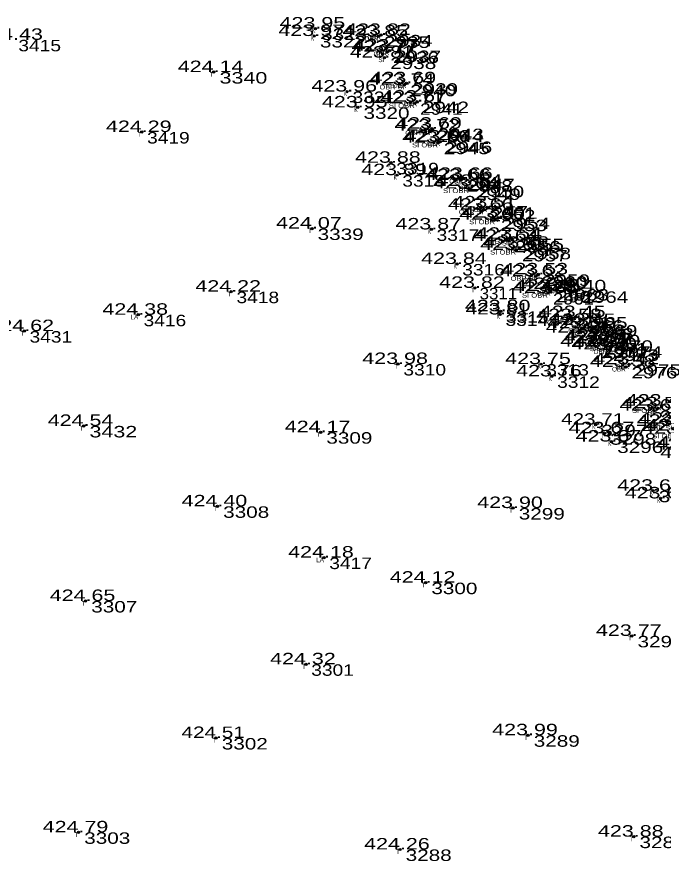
# Model space of a CAD drawing. Extents: x -639390 to -639074, y -1138747 to -1138358.
# Drawn here: x -639264.4 to -639222.1, y -1138514.5 to -1138459.3 of the extents above; entities that cross this region are included whole.
import ezdxf
from ezdxf.enums import TextEntityAlignment as Align

# ---------------------------------------------------------------- set-up
doc = ezdxf.new("R2010")
doc.units = 0
doc.header["$LTSCALE"] = 0.3
doc.header["$PDMODE"] = 32
doc.header["$PDSIZE"] = 0.15
for name, color, linetype in [('11', 7, 'Continuous'), ('12', 7, 'Continuous'), ('13', 7, 'Continuous'), ('57', 7, 'Continuous')]:
    doc.layers.add(name, color=color, linetype=linetype)

msp = doc.modelspace()

# ---------------------------------------------------------------- linework, layer by layer
at = {"layer": '11'}
for p in [(-639244.84, -1138460.09), (-639244.92, -1138460.58), (-639240.73, -1138460.61), (-639240.55, -1138460.51), (-639240.14, -1138461.6), (-639240, -1138461.53), (-639240.32, -1138461.99), (-639251.5, -1138462.94), (-639239.01, -1138463.77), (-639238.89, -1138463.67), (-639242.76, -1138464.21), (-639238.34, -1138464.98), (-639238.18, -1138464.87), (-639242.07, -1138465.25), (-639237.33, -1138466.76), (-639237.21, -1138466.64), (-639256.2, -1138466.86), (-639236.82, -1138467.56), (-639236.66, -1138467.48), (-639239.9, -1138468.87), (-639239.5, -1138469.68), (-639235.32, -1138470), (-639235.19, -1138469.92), (-639234.79, -1138470.55), (-639234.57, -1138470.38), (-639233.83, -1138471.94), (-639233.6, -1138471.79), (-639233.08, -1138472.59), (-639232.88, -1138472.45), (-639245.07, -1138473.17), (-639237.26, -1138473.23), (-639231.97, -1138473.84), (-639232.18, -1138473.98), (-639231.5, -1138474.43), (-639231.71, -1138474.57), (-639235.58, -1138475.49), (-639230.43, -1138476.29), (-639230.26, -1138476.17), (-639234.4, -1138477.05), (-639229.46, -1138477.25), (-639229.02, -1138477.13), (-639250.35, -1138477.3), (-639229.63, -1138477.39), (-639227.76, -1138477.28), (-639256.43, -1138478.81), (-639232.75, -1138478.79), (-639232.72, -1138478.58), (-639228.05, -1138479.16), (-639227.81, -1138478.96), (-639227.16, -1138479.48), (-639263.89, -1138479.88), (-639227.5, -1138479.98), (-639227.4, -1138479.69), (-639226.15, -1138480.48), (-639226.48, -1138480.89), (-639226.3, -1138480.66), (-639225.75, -1138481.08), (-639225.54, -1138480.87), (-639239.43, -1138482.03), (-639230.08, -1138482.04), (-639224.54, -1138482.22), (-639224.31, -1138482.05), (-639229.37, -1138482.84), (-639222.43, -1138484.93), (-639222.19, -1138484.75), (-639222.69, -1138485.08), (-639260.01, -1138486.08), (-639226.51, -1138486), (-639244.5, -1138486.49), (-639225.93, -1138486.56), (-639225.47, -1138487.1), (-639222.75, -1138490.32), (-639222.26, -1138490.82), (-639251.25, -1138491.34), (-639231.91, -1138491.45), (-639244.28, -1138494.69), (-639237.63, -1138496.33), (-639259.88, -1138497.53), (-639224.14, -1138499.81), (-639245.46, -1138501.67), (-639251.34, -1138506.49), (-639230.93, -1138506.31), (-639260.34, -1138512.66), (-639224.01, -1138512.94), (-639239.31, -1138513.78)]:
    msp.add_point(p, dxfattribs=at)

# ---------------------------------------------------------------- texts
at = {"layer": '12'}
for s, width, p in [('423.95 ', 1.4, (-639244.84, -1138460.09)), ('424.43 ', 1.4, (-639264.62, -1138460.83)), ('423.97 ', 1.4, (-639244.92, -1138460.58)), ('423.85 ', 1.4, (-639240.73, -1138460.61)), ('423.82 ', 1.4, (-639240.55, -1138460.51)), ('423.77 ', 1.4, (-639240.14, -1138461.6)), ('423.77 ', 1.4, (-639240, -1138461.53)), ('423.81 ', 1.35, (-639240.319, -1138461.99)), ('424.14 ', 1.4, (-639251.5, -1138462.94)), ('423.74 ', 1.4, (-639239.01, -1138463.77)), ('423.69 ', 1.4, (-639238.89, -1138463.67)), ('423.96 ', 1.4, (-639242.759, -1138464.21)), ('423.95 ', 1.4, (-639242.07, -1138465.25)), ('423.71 ', 1.35, (-639238.339, -1138464.98)), ('423.67 ', 1.4, (-639238.18, -1138464.87)), ('424.29 ', 1.4, (-639256.2, -1138466.86)), ('423.72 ', 1.4, (-639237.33, -1138466.76)), ('423.69 ', 1.4, (-639237.21, -1138466.64)), ('423.70 ', 1.4, (-639236.82, -1138467.56)), ('423.66 ', 1.4, (-639236.659, -1138467.48)), ('423.88 ', 1.4, (-639239.9, -1138468.87)), ('423.89 ', 1.4, (-639239.5, -1138469.68)), ('423.66 ', 1.4, (-639235.319, -1138470)), ('423.66 ', 1.4, (-639235.189, -1138469.92)), ('423.64 ', 1.4, (-639234.79, -1138470.55)), ('423.54 ', 1.4, (-639234.57, -1138470.38)), ('423.51 ', 1.35, (-639233.599, -1138471.79)), ('423.66 ', 1.4, (-639233.829, -1138471.94)), ('423.60 ', 1.4, (-639233.08, -1138472.59)), ('423.47 ', 1.4, (-639232.88, -1138472.45)), ('424.07 ', 1.4, (-639245.07, -1138473.17)), ('423.87 ', 1.4, (-639237.26, -1138473.23)), ('423.64 ', 1.4, (-639232.18, -1138473.98)), ('423.54 ', 1.4, (-639231.97, -1138473.84)), ('423.63 ', 1.4, (-639231.71, -1138474.57)), ('423.48 ', 1.4, (-639231.5, -1138474.43)), ('423.84 ', 1.4, (-639235.58, -1138475.49)), ('423.62 ', 1.4, (-639230.43, -1138476.29)), ('423.53 ', 1.4, (-639230.26, -1138476.17)), ('424.22 ', 1.4, (-639250.35, -1138477.3)), ('423.82 ', 1.4, (-639234.4, -1138477.05)), ('423.58 ', 1.4, (-639229.63, -1138477.39)), ('423.45 ', 1.4, (-639229.46, -1138477.25)), ('423.40 ', 1.4, (-639229.02, -1138477.13)), ('423.40 ', 1.4, (-639227.76, -1138477.28)), ('424.38 ', 1.4, (-639256.43, -1138478.81)), ('423.80 ', 1.4, (-639232.72, -1138478.58)), ('423.81 ', 1.35, (-639232.749, -1138478.79)), ('423.45 ', 1.4, (-639227.81, -1138478.96)), ('423.58 ', 1.4, (-639228.05, -1138479.16)), ('423.45 ', 1.4, (-639227.16, -1138479.48)), ('424.62 ', 1.4, (-639263.89, -1138479.88)), ('423.61 ', 1.35, (-639227.499, -1138479.98)), ('423.51 ', 1.35, (-639227.399, -1138479.69)), ('423.51 ', 1.35, (-639226.299, -1138480.66)), ('423.45 ', 1.4, (-639226.15, -1138480.48)), ('423.60 ', 1.4, (-639226.48, -1138480.89)), ('423.50 ', 1.4, (-639225.75, -1138481.08)), ('423.40 ', 1.4, (-639225.54, -1138480.87)), ('423.98 ', 1.4, (-639239.43, -1138482.03)), ('423.75 ', 1.4, (-639230.08, -1138482.04)), ('423.58 ', 1.4, (-639224.54, -1138482.22)), ('423.42 ', 1.4, (-639224.31, -1138482.05)), ('423.76 ', 1.4, (-639229.369, -1138482.84)), ('423.61 ', 1.35, (-639222.689, -1138485.08)), ('423.58 ', 1.4, (-639222.43, -1138484.93)), ('423.48 ', 1.4, (-639222.19, -1138484.75)), ('424.54 ', 1.4, (-639260.01, -1138486.08)), ('423.71 ', 1.35, (-639226.509, -1138486)), ('423.57 ', 1.4, (-639221.47, -1138486.07)), ('423.50 ', 1.4, (-639221.3, -1138485.93)), ('424.17 ', 1.4, (-639244.5, -1138486.49)), ('423.67 ', 1.4, (-639225.93, -1138486.56)), ('423.56 ', 1.4, (-639221.109, -1138486.59)), ('423.45 ', 1.4, (-639220.87, -1138486.38)), ('423.67 ', 1.4, (-639225.47, -1138487.1)), ('423.50 ', 1.4, (-639220.25, -1138487.64)), ('423.42 ', 1.4, (-639220.07, -1138487.49)), ('423.50 ', 1.4, (-639219.93, -1138488.18)), ('423.65 ', 1.4, (-639222.75, -1138490.32)), ('423.65 ', 1.4, (-639222.26, -1138490.82)), ('424.40 ', 1.4, (-639251.25, -1138491.34)), ('423.90 ', 1.4, (-639231.91, -1138491.45)), ('424.18 ', 1.4, (-639244.28, -1138494.69)), ('424.12 ', 1.4, (-639237.63, -1138496.33)), ('424.65 ', 1.4, (-639259.88, -1138497.53)), ('423.77 ', 1.4, (-639224.14, -1138499.81)), ('424.32 ', 1.4, (-639245.46, -1138501.67)), ('424.51 ', 1.35, (-639251.339, -1138506.49)), ('423.99 ', 1.4, (-639230.93, -1138506.31)), ('424.79 ', 1.4, (-639260.34, -1138512.66)), ('423.88 ', 1.4, (-639224.01, -1138512.94)), ('424.26 ', 1.4, (-639239.309, -1138513.78))]:
    msp.add_text(s, height=0.75, dxfattribs=dict(at, width=width)).set_placement(p, align=Align.CENTER)
at = {"layer": '13'}
for s, width, p in [(' 3323', 1.35, (-639244.84, -1138460.84)), (' 3322', 1.35, (-639244.92, -1138461.33)), (' 2935', 1.35, (-639240.73, -1138461.36)), (' 2934', 1.35, (-639240.55, -1138461.26)), (' 3415', 1.25, (-639264.62, -1138461.58)), (' 2936', 1.35, (-639240.14, -1138462.35)), (' 2937', 1.35, (-639240, -1138462.28)), (' 2938', 1.35, (-639240.32, -1138462.74)), (' 3340', 1.4, (-639251.5, -1138463.69)), (' 2940', 1.35, (-639239.01, -1138464.52)), (' 2939', 1.35, (-639238.89, -1138464.42)), (' 3321', 1.25, (-639242.76, -1138464.96)), (' 2941', 1.25, (-639238.34, -1138465.73)), (' 2942', 1.35, (-639238.18, -1138465.62)), (' 3320', 1.35, (-639242.07, -1138466)), (' 2943', 1.35, (-639237.21, -1138467.39)), (' 3419', 1.25, (-639256.2, -1138467.61)), (' 2944', 1.4, (-639237.33, -1138467.51)), (' 2945', 1.35, (-639236.82, -1138468.31)), (' 2946', 1.35, (-639236.66, -1138468.23)), (' 3319', 1.25, (-639239.9, -1138469.62)), (' 3318', 1.25, (-639239.5, -1138470.43)), (' 2948', 1.35, (-639235.32, -1138470.75)), (' 2947', 1.35, (-639235.19, -1138470.67)), (' 2949', 1.35, (-639234.79, -1138471.3)), (' 2950', 1.35, (-639234.57, -1138471.13)), (' 2952', 1.35, (-639233.83, -1138472.69)), (' 2951', 1.25, (-639233.6, -1138472.54)), (' 2953', 1.35, (-639233.08, -1138473.34)), (' 2954', 1.35, (-639232.88, -1138473.2)), (' 3339', 1.35, (-639245.07, -1138473.92)), (' 3317', 1.25, (-639237.26, -1138473.98)), (' 2955', 1.35, (-639231.97, -1138474.59)), (' 2956', 1.35, (-639232.18, -1138474.73)), (' 2958', 1.35, (-639231.5, -1138475.18)), (' 2957', 1.35, (-639231.71, -1138475.32)), (' 3316', 1.25, (-639235.58, -1138476.24)), (' 2960', 1.35, (-639230.43, -1138477.04)), (' 2959', 1.35, (-639230.26, -1138476.92)), (' 3311', 1.1, (-639234.4, -1138477.8)), (' 2963', 1.35, (-639229.02, -1138477.88)), (' 3418', 1.25, (-639250.35, -1138478.05)), (' 2961', 1.2, (-639229.63, -1138478.14)), (' 2962', 1.35, (-639229.46, -1138478)), (' 2964', 1.35, (-639227.76, -1138478.03)), (' 3416', 1.25, (-639256.43, -1138479.56)), (' 3314', 1.25, (-639232.75, -1138479.54)), (' 3315', 1.25, (-639232.72, -1138479.33)), (' 2966', 1.35, (-639228.05, -1138479.91)), (' 2965', 1.35, (-639227.81, -1138479.71)), (' 3431', 1.25, (-639263.89, -1138480.63)), (' 2968', 1.35, (-639227.4, -1138480.44)), (' 2969', 1.35, (-639227.16, -1138480.23)), (' 2967', 1.35, (-639227.5, -1138480.73)), (' 2970', 1.35, (-639226.15, -1138481.23)), (' 2972', 1.35, (-639226.48, -1138481.64)), (' 2971', 1.25, (-639226.3, -1138481.41)), (' 2974', 1.35, (-639225.54, -1138481.62)), (' 2973', 1.35, (-639225.75, -1138481.83)), (' 3310', 1.25, (-639239.43, -1138482.78)), (' 3313', 1.25, (-639230.08, -1138482.79)), (' 2975', 1.35, (-639224.31, -1138482.8)), (' 2976', 1.35, (-639224.54, -1138482.97)), (' 3312', 1.25, (-639229.37, -1138483.59)), (' 2977', 1.35, (-639222.69, -1138485.83)), (' 3297', 1.35, (-639226.51, -1138486.75)), (' 3432', 1.4, (-639260.01, -1138486.83)), (' 3309', 1.35, (-639244.5, -1138487.24)), (' 3298', 1.35, (-639225.93, -1138487.31)), (' 3296', 1.35, (-639225.47, -1138487.85)), (' 3295', 1.35, (-639222.75, -1138491.07)), (' 3308', 1.35, (-639251.25, -1138492.09)), (' 3299', 1.35, (-639231.91, -1138492.2)), (' 3417', 1.25, (-639244.28, -1138495.44)), (' 3300', 1.35, (-639237.63, -1138497.08)), (' 3307', 1.35, (-639259.88, -1138498.28)), (' 3290', 1.35, (-639224.14, -1138500.56)), (' 3301', 1.25, (-639245.46, -1138502.42)), (' 3289', 1.35, (-639230.93, -1138507.06)), (' 3302', 1.35, (-639251.34, -1138507.24)), (' 3303', 1.35, (-639260.34, -1138513.41)), (' 3282', 1.35, (-639224.01, -1138513.69)), (' 3288', 1.35, (-639239.31, -1138514.53))]:
    msp.add_text(s, height=0.75, dxfattribs=dict(at, width=width)).set_placement(p)
at = {"layer": '57'}
for s, width, p in [('K', 0.65, (-639244.919, -1138460.88)), ('K', 0.65, (-639244.839, -1138460.39)), ('OBR', 0.9, (-639240.729, -1138460.91)), ('OBR', 0.9, (-639240.549, -1138460.81)), ('OBR', 0.9, (-639240.139, -1138461.9)), ('OBR', 0.9, (-639239.999, -1138461.83)), ('SI', 1.05, (-639240.32, -1138462.29)), ('T', 0.85, (-639251.5, -1138463.24)), ('OBR SI', 1.2, (-639239.01, -1138464.07)), ('OBR', 0.9, (-639238.889, -1138463.97)), ('K', 0.65, (-639242.759, -1138464.51)), ('SI OBR', 1.25, (-639238.339, -1138465.28)), ('OBR', 0.9, (-639238.179, -1138465.17)), ('K', 0.65, (-639242.069, -1138465.55)), ('OBR', 0.9, (-639237.209, -1138466.94)), ('T', 0.85, (-639256.2, -1138467.16)), ('OBR SI', 1.2, (-639237.33, -1138467.06)), ('SI OBR', 1.25, (-639236.819, -1138467.86)), ('OBR', 0.9, (-639236.659, -1138467.78)), ('K', 0.65, (-639239.899, -1138469.17)), ('K', 0.65, (-639239.499, -1138469.98)), ('OBR', 0.9, (-639235.189, -1138470.22)), ('SI', 1.05, (-639235.32, -1138470.3)), ('SI OBR', 1.25, (-639234.789, -1138470.85)), ('OBR', 0.9, (-639234.569, -1138470.68)), ('OBR SI', 1.2, (-639233.83, -1138472.24)), ('OBR', 0.9, (-639233.599, -1138472.09)), ('SI OBR', 1.25, (-639233.079, -1138472.89)), ('OBR', 0.9, (-639232.879, -1138472.75)), ('T', 0.85, (-639245.07, -1138473.47)), ('K', 0.65, (-639237.259, -1138473.53)), ('OBR', 0.9, (-639231.969, -1138474.14)), ('OBR SI', 1.2, (-639232.18, -1138474.28)), ('OBR', 0.9, (-639231.499, -1138474.73)), ('SI OBR', 1.25, (-639231.709, -1138474.87)), ('K', 0.65, (-639235.579, -1138475.79)), ('OBR SI', 1.2, (-639230.43, -1138476.59)), ('OBR', 0.9, (-639230.259, -1138476.47)), ('T', 0.85, (-639234.4, -1138477.35)), ('SA', 0.95, (-639229.02, -1138477.43)), ('T', 0.85, (-639250.35, -1138477.6)), ('SI OBR', 1.25, (-639229.629, -1138477.69)), ('OBR', 0.9, (-639229.459, -1138477.55)), ('SA', 0.95, (-639227.76, -1138477.58)), ('K', 0.65, (-639232.749, -1138479.09)), ('K', 0.65, (-639232.719, -1138478.88)), ('OBR SI', 1.2, (-639228.05, -1138479.46)), ('OBR', 0.9, (-639227.809, -1138479.26)), ('T', 0.85, (-639263.89, -1138480.18)), ('OBR', 0.9, (-639227.399, -1138479.99)), ('OBR', 0.9, (-639227.159, -1138479.78)), ('SI', 1.05, (-639227.5, -1138480.28)), ('OBR', 0.9, (-639226.149, -1138480.78)), ('OBR', 0.9, (-639226.299, -1138480.96)), ('SI', 1.05, (-639226.48, -1138481.19)), ('OBR', 0.9, (-639225.539, -1138481.17)), ('OBR', 0.9, (-639225.749, -1138481.38)), ('T', 0.85, (-639239.43, -1138482.33)), ('K', 0.65, (-639230.079, -1138482.34)), ('OBR', 0.9, (-639224.309, -1138482.35)), ('OBR', 0.9, (-639224.539, -1138482.52)), ('K', 0.65, (-639229.369, -1138483.14)), ('SI OBR', 1.25, (-639222.429, -1138485.23)), ('OBR', 0.9, (-639222.189, -1138485.05)), ('SI', 1.05, (-639222.69, -1138485.38)), ('K', 0.65, (-639226.509, -1138486.3)), ('T', 0.85, (-639260.01, -1138486.38)), ('T', 0.85, (-639244.5, -1138486.79)), ('T', 0.85, (-639225.93, -1138486.86)), ('OBR SI', 1.2, (-639221.47, -1138486.37)), ('K', 0.65, (-639225.469, -1138487.4)), ('SI OBR', 1.25, (-639221.109, -1138486.89)), ('K', 0.65, (-639222.749, -1138490.62)), ('K', 0.65, (-639222.259, -1138491.12)), ('T', 0.85, (-639251.25, -1138491.64)), ('T', 0.85, (-639231.91, -1138491.75)), ('T', 0.85, (-639237.63, -1138496.63)), ('T', 0.85, (-639259.88, -1138497.83)), ('T', 0.85, (-639224.14, -1138500.11)), ('T', 0.85, (-639245.46, -1138501.97)), ('T', 0.85, (-639230.93, -1138506.61)), ('T', 0.85, (-639251.34, -1138506.79)), ('T', 0.85, (-639260.34, -1138512.96)), ('T', 0.85, (-639224.01, -1138513.24)), ('T', 0.85, (-639239.31, -1138514.08))]:
    msp.add_text(s, height=0.3, dxfattribs=dict(at, width=width)).set_placement(p, align=Align.RIGHT)
for p in [(-639256.43, -1138479.11), (-639244.28, -1138494.99)]:
    msp.add_text('LA', height=0.3, dxfattribs=at).set_placement(p, align=Align.RIGHT)

doc.saveas('drawing.dxf')
